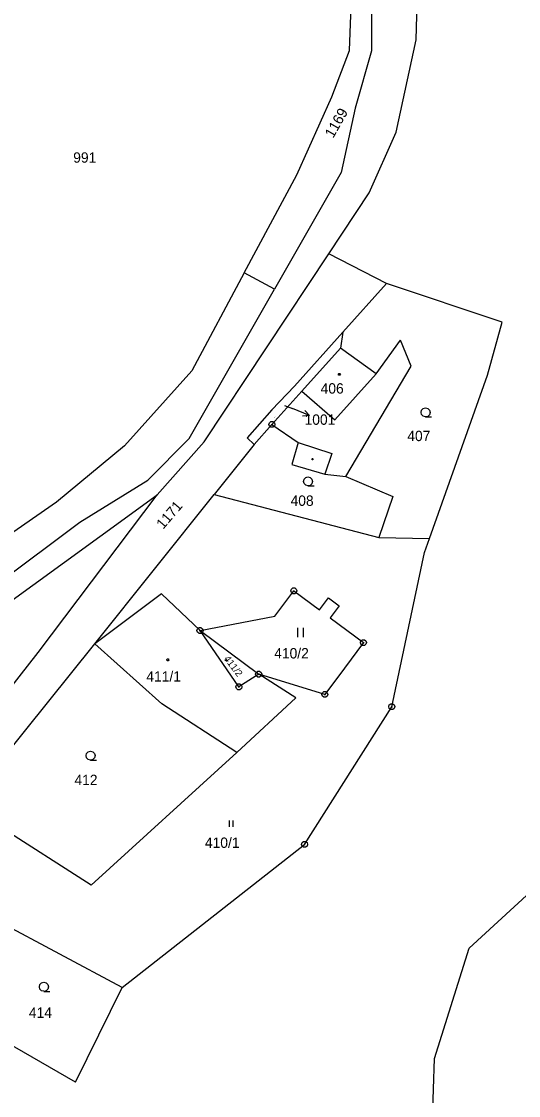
# Model space of a CAD drawing. Extents: x -812394 to -807601, y -1013098 to -1009266.
# Drawn here: x -810837.1 to -810755.5, y -1011688.8 to -1011512.4 of the extents above; entities that cross this region are included whole.
import ezdxf

# ---------------------------------------------------------------- set-up
doc = ezdxf.new("R2010")
doc.units = 0
for name, color, linetype in [('KN_HRANICE', 7, 'Continuous'), ('KN_KULTURY', 7, 'Continuous'), ('KN_MEZNIKY', 7, 'Continuous'), ('KN_PARCELY', 7, 'Continuous'), ('KN_SLUCKY', 7, 'Continuous')]:
    doc.layers.add(name, color=color, linetype=linetype)

# ---------------------------------------------------------------- blocks, each defined once
blk = doc.blocks.new('304')
blk.add_lwpolyline([(0, 0), (-0.38, 0.1), (-0.65, 0.37), (-0.75, 0.74), (-0.65, 1.11), (-0.38, 1.38), (-0.01, 1.48), (0.36, 1.38), (0.63, 1.11), (0.73, 0.73), (0.63, 0.35), (0.36, 0.08), (-0.02, -0.02), (0.98, -0.02)])
blk = doc.blocks.new('306')
for p, q in [((-0.5, 1.5), (-0.5, 0)), ((0.5, 0), (0.5, 1.5))]:
    blk.add_line(p, q)
blk = doc.blocks.new('NAHRADNI_SYMBOL')
blk.add_lwpolyline([(0.09, 0.15), (0.18, 0), (0.09, -0.15), (-0.09, -0.15), (-0.18, 0), (-0.09, 0.15), (0.09, 0.15)])
blk = doc.blocks.new('10292')
blk.add_line((0, 3), (0, 0))
blk.add_lwpolyline([(-0.5, 2), (0, 3), (0.5, 2)])
blk = doc.blocks.new('402')
blk.add_lwpolyline([(0.09, 0.15), (0.18, 0), (0.09, -0.15), (-0.09, -0.15), (-0.18, 0), (-0.09, 0.15), (0.09, 0.15)])
blk = doc.blocks.new('105')
blk.add_line((-0.12, 0), (0.12, 0))
blk.add_lwpolyline([(0.15, 0.48), (0.4, 0.3), (0.5, 0.01), (0.4, -0.28), (0.15, -0.46), (-0.16, -0.46), (-0.41, -0.28), (-0.51, 0.01), (-0.41, 0.3), (-0.16, 0.48), (0.15, 0.48)])

msp = doc.modelspace()

# ---------------------------------------------------------------- linework, layer by layer
at = {"layer": 'KN_HRANICE'}
for p, q in [((-810783.24, -1011517.2), (-810782.75, -1011503.15)), ((-810786.16, -1011524.78), (-810783.24, -1011517.2)), ((-810791.91, -1011537.6), (-810786.16, -1011524.78)), ((-810782.3, -1011526.63), (-810784.63, -1011537.23)), ((-810800.53, -1011553.7), (-810791.91, -1011537.6)), ((-810784.63, -1011537.23), (-810795.57, -1011556.36)), ((-810777.16, -1011555.46), (-810786.65, -1011550.55)), ((-810800.53, -1011553.7), (-810809.15, -1011569.79)), ((-810795.57, -1011556.36), (-810800.53, -1011553.7)), ((-810809.59, -1011580.88), (-810795.57, -1011556.36)), ((-810777.16, -1011555.46), (-810784.33, -1011563.43)), ((-810758.13, -1011561.79), (-810777.16, -1011555.46)), ((-810760.56, -1011570.51), (-810758.13, -1011561.79)), ((-810784.33, -1011563.43), (-810784.69, -1011566.07)), ((-810778.84, -1011570.27), (-810774.83, -1011564.74)), ((-810773.09, -1011568.99), (-810774.83, -1011564.74)), ((-810784.69, -1011566.07), (-810791.05, -1011573.12)), ((-810778.84, -1011570.27), (-810784.69, -1011566.07)), ((-810783.83, -1011587.16), (-810773.09, -1011568.99)), ((-810809.15, -1011569.79), (-810820.21, -1011582.08)), ((-810770.11, -1011597.34), (-810760.56, -1011570.51)), ((-810791.05, -1011573.12), (-810795.98, -1011578.6)), ((-810795.98, -1011578.6), (-810798.92, -1011581.87)), ((-810795.98, -1011578.6), (-810791.67, -1011581.54)), ((-810816.35, -1011587.73), (-810809.59, -1011580.88)), ((-810798.92, -1011581.87), (-810805.49, -1011590.1)), ((-810791.67, -1011581.54), (-810792.74, -1011585.15)), ((-810820.21, -1011582.08), (-810831.4, -1011591.35)), ((-810792.74, -1011585.15), (-810787.3, -1011586.77)), ((-810787.3, -1011586.77), (-810783.83, -1011587.16)), ((-810783.83, -1011587.16), (-810776.13, -1011590.43)), ((-810827.53, -1011594.64), (-810816.35, -1011587.73)), ((-810825.11, -1011614.6), (-810805.49, -1011590.1)), ((-810824.29, -1011596.97), (-810814.84, -1011590.15)), ((-810805.49, -1011590.1), (-810778.39, -1011597.16)), ((-810776.13, -1011590.43), (-810778.39, -1011597.16)), ((-810831.4, -1011591.35), (-810863.67, -1011613.78)), ((-810851.23, -1011612.3), (-810827.53, -1011594.64)), ((-810849.63, -1011615.36), (-810824.29, -1011596.97)), ((-810778.39, -1011597.16), (-810770.11, -1011597.34)), ((-810770.92, -1011599.62), (-810770.11, -1011597.34)), ((-810776.29, -1011624.93), (-810770.92, -1011599.62)), ((-810814.15, -1011606.38), (-810825.11, -1011614.6)), ((-810807.8, -1011612.43), (-810814.15, -1011606.38)), ((-810795.48, -1011610.09), (-810792.38, -1011605.92)), ((-810792.38, -1011605.92), (-810788.17, -1011609.04)), ((-810788.17, -1011609.04), (-810786.71, -1011607.08)), ((-810786.71, -1011607.08), (-810784.94, -1011608.39)), ((-810807.8, -1011612.43), (-810795.48, -1011610.09)), ((-810784.94, -1011608.39), (-810786.4, -1011610.35)), ((-810786.4, -1011610.35), (-810780.94, -1011614.41)), ((-810801.41, -1011621.68), (-810807.8, -1011612.43)), ((-810807.8, -1011612.43), (-810798.15, -1011619.6)), ((-810840.43, -1011633.72), (-810825.11, -1011614.6)), ((-810814.09, -1011624.47), (-810825.11, -1011614.6)), ((-810780.94, -1011614.41), (-810784.04, -1011618.58)), ((-810784.04, -1011618.58), (-810787.28, -1011622.93)), ((-810798.15, -1011619.6), (-810801.41, -1011621.68)), ((-810787.28, -1011622.93), (-810798.15, -1011619.6)), ((-810792.08, -1011623.48), (-810798.15, -1011619.6)), ((-810792.08, -1011623.48), (-810801.74, -1011632.47)), ((-810801.74, -1011632.47), (-810814.09, -1011624.47)), ((-810790.62, -1011647.55), (-810776.29, -1011624.93)), ((-810801.74, -1011632.47), (-810825.68, -1011654.24)), ((-810825.68, -1011654.24), (-810846.16, -1011641.14)), ((-810820.6, -1011671.03), (-810790.62, -1011647.55)), ((-810763.59, -1011664.59), (-810749.89, -1011651.97)), ((-810820.6, -1011671.03), (-810845.13, -1011657.96)), ((-810769.26, -1011682.72), (-810763.59, -1011664.59)), ((-810828.27, -1011686.59), (-810820.6, -1011671.03)), ((-810828.27, -1011686.59), (-810844.35, -1011677.34)), ((-810770.67, -1011728.15), (-810769.26, -1011682.72))]:
    msp.add_line(p, q, dxfattribs=at)
for points in [[(-810782.41, -1011459.43), (-810781.54, -1011476.23), (-810779.65, -1011504.07), (-810779.6, -1011517.24), (-810782.3, -1011526.63)], [(-810786.65, -1011550.55), (-810780.03, -1011540.57), (-810775.59, -1011530.62), (-810772.3, -1011515.42), (-810772.06, -1011507.46), (-810775.87, -1011475.3)], [(-810814.84, -1011590.15), (-810807.13, -1011581.45), (-810786.65, -1011550.55)], [(-810784.33, -1011563.43), (-810792.3, -1011572.28), (-810795.98, -1011576.16), (-810800.04, -1011580.78), (-810798.92, -1011581.87)], [(-810845.57, -1011630.24), (-810834.41, -1011616.01), (-810814.84, -1011590.15)]]:
    msp.add_lwpolyline(points, dxfattribs=at)
at = {"layer": 'KN_PARCELY'}
msp.add_line((-810793.9, -1011575.45), (-810792.61, -1011575.98), dxfattribs=at)
at = {"layer": 'KN_SLUCKY'}
for p, q in [((-810785.63, -1011577.82), (-810778.84, -1011570.27)), ((-810791.05, -1011573.12), (-810785.63, -1011577.82)), ((-810791.67, -1011581.54), (-810786.13, -1011583.33)), ((-810786.13, -1011583.33), (-810787.3, -1011586.77))]:
    msp.add_line(p, q, dxfattribs=at)

# ---------------------------------------------------------------- block references
at = {"layer": 'KN_KULTURY'}
for name, p in [('402', (-810784.91, -1011570.35)), ('304', (-810770.73, -1011577.34)), ('304', (-810790.05, -1011588.67)), ('306', (-810791.28, -1011613.49)), ('NAHRADNI_SYMBOL', (-810813.1, -1011617.23)), ('304', (-810825.78, -1011633.7)), ('304', (-810833.45, -1011671.66))]:
    msp.add_blockref(name, p, dxfattribs=at)
at = {"layer": 'KN_KULTURY', "xscale": 0.67, "yscale": 0.67}
for name, p in [('402', (-810789.32, -1011584.29)), ('NAHRADNI_SYMBOL', (-810803.56, -1011617.27)), ('306', (-810802.7, -1011644.63))]:
    msp.add_blockref(name, p, dxfattribs=at)
at = {"layer": 'KN_MEZNIKY'}
for p in [(-810795.98, -1011578.6), (-810792.38, -1011605.92), (-810807.8, -1011612.43), (-810780.94, -1011614.41), (-810798.15, -1011619.6), (-810801.41, -1011621.68), (-810787.28, -1011622.93), (-810776.29, -1011624.93), (-810790.62, -1011647.55)]:
    msp.add_blockref('105', p, dxfattribs=at)
at = {"layer": 'KN_PARCELY', "rotation": -112.25304900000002}
msp.add_blockref('10292', (-810792.61, -1011575.98), dxfattribs=at)

# ---------------------------------------------------------------- texts
at = {"layer": 'KN_PARCELY'}
for s, height, rotation, p in [('1169', 1.7, 60.332, (-810785.92, -1011531.67)), ('1001', 0.1, 49.217, (-810795.57, -1011577.52)), ('1171', 1.7, 49.389, (-810813.86, -1011595.89)), ('411/2', 1.14, 307.22, (-810803.92, -1011617.08))]:
    msp.add_text(s, height=height, rotation=rotation, dxfattribs=at).set_placement(p)
for s, p in [('991', (-810828.64, -1011535.61)), ('406', (-810787.98, -1011573.52)), ('1001', (-810790.62, -1011578.64)), ('407', (-810773.74, -1011581.32)), ('408', (-810792.92, -1011591.95)), ('410/2', (-810795.61, -1011617.01)), ('411/1', (-810816.62, -1011620.81)), ('412', (-810828.44, -1011637.81)), ('410/1', (-810807, -1011648.11)), ('414', (-810835.93, -1011676.02))]:
    msp.add_text(s, height=1.7, dxfattribs=at).set_placement(p)

doc.saveas('drawing.dxf')
